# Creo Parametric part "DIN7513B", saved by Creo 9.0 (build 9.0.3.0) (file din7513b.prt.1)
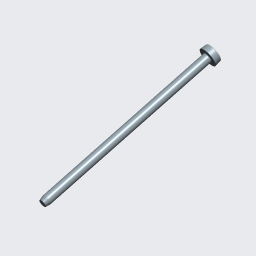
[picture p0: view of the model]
Units: Custom; MM, POUND, SECS

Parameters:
  PLACEMENT = "A"

Other parameters: D7, D6, D16, D15, THREADS_PER_INCH

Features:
  1. datum plane "DTM1"
  2. datum plane "DTM2"
  3. datum plane "DTM3"
  4. cut
  5. round
  6. round
  7. cut

Other named items: THRU

Named dimensions: basic_dia

Layers: 1, 2, 3, 4, 5, 6, 7, 8, 9, 10, 11, 12, 13, 14, 15, 16, 17, 18, 19, 20, 21, 22, 23, 24, 25, 26, 27, 28, 29, 30, 31, 32, FLAECHEN, FLAECHENVERBUND, GEOM.ELEMENT, KONSTR.ELEMENT

Family table entries: DIN7513M2_5B, DIN7513B, DIN7513M2_5BX6, DIN7513M2_5B, value(d_val), value(i_val), DIN7513M2_5BX8, DIN7513M2_5B, &/ , DIN7513M2_5BX10, DIN7513M2_5B, &/$, DIN7513M2_5BX12, DIN7513M2_5B, &/(, %2-T, 2-T, DIN7513M2_5BX16, DIN7513M2_5B, &/0, DIN7513M2_5BX20, DIN7513M2_5B, &/4, d11, DIN7513M3B, DIN7513B, DIN7513M3BX6, DIN7513M3B, value(s_val), _DIN7513M3BX6, IPRO_MP_CSYS, data(checksum_info), DIN7513M3BX8, DIN7513M3B, 2/ , Xlh, Xlh, DIN7513M3BX10, DIN7513M3B, &/$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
